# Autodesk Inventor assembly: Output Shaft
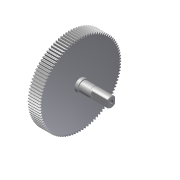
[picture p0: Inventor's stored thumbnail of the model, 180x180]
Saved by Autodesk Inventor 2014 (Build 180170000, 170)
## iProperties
Created: 2011-01
Part Number: Output Shaft
Document SubType Name: Assembly
Designer: Beta-8540w
ClientObjectVersion: 1
Author: Beta-8540w
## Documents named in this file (2)
- C:\Inventor 2014 Essentials\Assemblies\Chapter 09\Design Accelerators\Shaft c09-01.iam
- C:\Inventor 2014 Essentials\Assemblies\Chapter 09\Design Accelerators\Shaft c09-01.ipt
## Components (1 placed, 1 different names)
1. Input Shaft:1
